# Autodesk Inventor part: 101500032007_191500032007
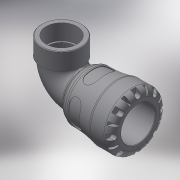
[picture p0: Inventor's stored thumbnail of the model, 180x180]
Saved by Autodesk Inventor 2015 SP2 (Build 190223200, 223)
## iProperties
Created: 2016-12
Part Number: 101500032007_191500032007
Material: Generic
Description: PLASSON 90° ELBOW WITH THREADED FEMALE OFFTAKE 32X3/4" SERIES 1
Document SubType Name: Modeling
Designer: KIM
Mass: 557.611 g
Surface Area: 990.043 cm^2
Volume: 557.611 cm^3
Density: 1 g/cm^3
Appearance: Default
Author: KIM
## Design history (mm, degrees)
derived "1015.ipt"
feature "Solid1::1015.ipt"
tag "TaggingFeature1"
body "Solid1"
other parameters: "d1" = 22.68, "d2" = 32, "d4" = 58, "d8" = 51.04, "d13" = 7.2, "d14" = 7.2, "d15" = 0, "d17" = 360 deg, "d19" = 8 deg, "d20" = 0.64, "d21" = 0.64, "d22" = 8 deg, "d24" = 0, "d26" = 360 deg, "d33" = 5.8, "d43" = 47.56, "d51" = 0.58, "d54" = 11.2, "d55" = 7.04, "d57" = 14.112, "d58" = 0, "d74" = 0, "d78" = 54, "d82" = 0.64, "d115" = 360 deg, "d207" = 90 deg, "d228" = 9.52, "d247" = 1.16, "d248" = 3.24, "d268" = 28.072, "d269" = 3.24, "d270" = 83, "d279" = 45, "d281" = 3.61755, "d294" = 24.117, "d295" = 18, "d296" = 19.8, "d297" = 21.7053, "d299" = 28.21689, "d300" = 21.7053, "d301" = 0, "d302" = 0, "d303" = 9.67155, "d306" = 0, "d307" = 9, "d308" = 8, "d310" = 3, "d_" = 32, "E_" = 58, "l_" = 54, "A_" = 83, "A_1" = 45, "l_2" = 18, "Rp_" = 24.117, "d9" = 9, "d11" = 58, "d298" = 31.3521
